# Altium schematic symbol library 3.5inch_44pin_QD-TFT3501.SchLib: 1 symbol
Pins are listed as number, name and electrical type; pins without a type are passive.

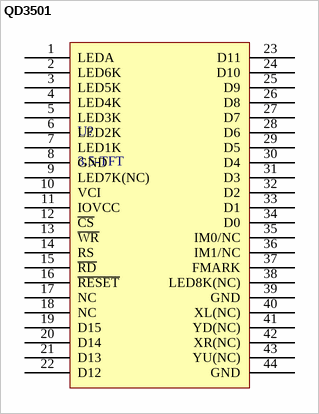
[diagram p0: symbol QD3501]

## QD3501
designator U?, comment 3.5-TFT
3.5inch TFT LCD
pins: 1 LEDA, 2 LED6K, 3 LED5K, 4 LED4K, 5 LED3K, 6 LED2K, 7 LED1K, 8 GND, 9 LED7K(NC), 10 VCI, 11 IOVCC, 12 ~{CS}, 13 ~{WR}, 14 RS, 15 ~{RD}, 16 ~{RESET}, 17 NC, 18 NC, 19 D15, 20 D14, 21 D13, 22 D12, 23 D11, 24 D10, 25 D9, 26 D8, 27 D7, 28 D6, 29 D5, 30 D4, 31 D3, 32 D2, 33 D1, 34 D0, 35 IM0/NC, 36 IM1/NC, 37 FMARK, 38 LED8K(NC), 39 GND, 40 XL(NC), 41 YD(NC), 42 XR(NC), 43 YU(NC), 44 GND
